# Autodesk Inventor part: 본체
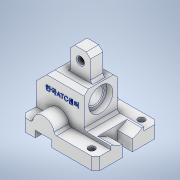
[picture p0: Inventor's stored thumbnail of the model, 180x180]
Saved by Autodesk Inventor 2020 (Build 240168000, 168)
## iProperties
Created: 2022-08
Part Number: 본체
Material: 알루미늄 6061
Document SubType Name: Modeling
Designer: com
Density: 2.7 g/cm^3
Appearance: 알루미늄 - 평지
Mass: 499.243 g
Surface Area: 337.564 cm^2
Volume: 184.905 cm^3
Author: com
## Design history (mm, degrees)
sketch "스케치1"
  geometry: L1 (18, 60)-(58, 60); L2 (58, 60)-(58, 19); L3 (58, 19)-(90, 19); L4 (90, 19)-(90, 0); L5 (90, 0)-(0, 0); L6 (0, 0)-(0, 42); L7 (0, 42)-(18, 60); 1 further point
  constraints: 14 end point, 5 perpendicular, 1 horizontal
  dimensions: "d0" = 45 deg angle of L1 L7; "d1" = 90 distance between parallel lines of L4 L6; "d2" = 0 distance from line of point (0, 0) L6; "d3" = 18 distance from line of L1 L6.end; "d4" = 60 distance between parallel lines of L1 L5; "d5" = 0 distance from line of point (0, 0) L5; "d6" = 32 distance between parallel lines of L4 L2; "d7" = 19 distance between parallel lines of L5 L3
extrude "돌출1" new body sketch "스케치1" stored distance "d8" = 40; taper "d9" = 0 deg
sketch "스케치3"
  geometry: L1 (0, 42)-(0, 0) reference; L2 (90, 19)-(90, 0) reference; L3 (0, 0)-(90, 0); L4 (90, 0)-(90, 15); L5 (0, 15)-(0, 0); L6 (90, 15)-(40, 15); L7 (14, 15)-(0, 15); A1 r 13 centre (27, 15) between (40, 15) and (14, 15); 2 further points
  constraints: 10 end point, 3 parallel, 2 point on circle, 2 point on line, 1 centre point, 1 horizontal, 1 perpendicular
  dimensions: "d11" = 26 diameter of A1; "d12" = 27 distance from line of A1.centre L1; "d13" = 15 distance between parallel lines of L3 L7; "d14" = 15 distance between parallel lines of L3 L6
extrude "돌출2" join sketch "스케치3" stored distance "d15" = 76; taper "d16" = 0 deg
sketch "스케치4"
  geometry: L1 (17, 8)-(37, 8); L2 (37, 8)-(37, -5.385); L3 (37, -5.385)-(17, -5.385); L4 (17, -5.385)-(17, 8); L5 (0, 0)-(0, 15) reference; L6 (90, 0)-(0, 0) reference; 1 further point
  constraints: 8 end point, 2 parallel, 1 horizontal, 1 midpoint, 1 perpendicular
  dimensions: "d17" = 20 distance between parallel lines of L2 L4; "d18" = 27 distance from line of point (27, 8) L5; "d19" = 8 distance between parallel lines of L1 L6
extrude "돌출3" cut sketch "스케치4" extent not by distance; stored distance "d20" = 38; taper "d21" = 0 deg
sketch "스케치5"
  geometry: L1 (18, 60)-(58, 60) reference; L2 (29, 90)-(53, 90); L3 (53, 90)-(53, 60); L4 (53, 60)-(29, 60); L5 (29, 60)-(29, 90); L6 (58, 19)-(58, 60) reference; L7 (37, 0)-(90, 0) reference; C1 r 4 at (41, 77); 2 further points
  constraints: 8 end point, 2 parallel, 1 centre point, 1 horizontal, 1 perpendicular, 1 point on line
  dimensions: "d22" = 30 distance of L4.end L2.start; "d23" = 24 distance of L2.start L2.end; "d24" = 5 distance between parallel lines of L6 L3; "d25" = 8 diameter of C1; "d26" = 12 distance from line of L5 C1.centre; "d27" = 77 distance from line of L7 C1.centre
extrude "돌출4" join sketch "스케치5" stored distance "d28" = 15; taper "d29" = 0 deg
chamfer "모따기1" distance "d30" = 5; stored, may be unused: second distance "d31" = 2, angle "d32" = 45 deg
fillet "모깎기1" dims "d33" = 3
fillet "모깎기2" dims "d34" = 3
chamfer "모따기2" distance "d35" = 5; stored, may be unused: second distance "d36" = 2, angle "d37" = 45 deg
sketch "스케치6"
  geometry: L1 (47.284, 53)-(47.284, -13) reference; 3 further points
  dimensions: "d38" = 30 vertical distance of point (34.284, 50) point (-42.716, 20); "d39" = 60 distance of point (34.284, -10) point (34.284, 50); "d40" = 13 distance from line of L1 point (34.284, 50); "d41" = 13 distance from line of L1 point (34.284, -10)
hole "구멍1" sketch "스케치6" at (34.284, -10), (34.284, 50) diameter "d42" = 4.5; stored, may be unused: countersink angle "d46" = 90 deg, drill point angle "d48" = 118 deg; dims "d43" = 6, "d44" = 8, "d45" = 4.4, "d47" = 8
chamfer "모따기3" distance "d49" = 5; stored, may be unused: second distance "d50" = 2, angle "d51" = 45 deg
sketch "스케치8"
  geometry: L1 (60.58, 42)-(-5.69, 42); L2 (60.58, 42)-(67.958, 42); L3 (37, 0)-(85, 0) reference; L4 (60.58, 42)-(60.58, 56.5); L5 (60.58, 56.5)-(51, 56.5); L6 (51, 56.5)-(51, 52); L7 (51, 52)-(-5.69, 52); L8 (-5.69, 52)-(-5.69, 42); L9 (58, 19)-(58, 55) reference; 1 further point
  constraints: 14 end point, 4 perpendicular, 2 horizontal, 1 vertical
  dimensions: "d53" = 42 distance between parallel lines of L2 L3; "d54" = 29 diameter of L5 L2; "d55" = 20 diameter of L7 L2; "d56" = 7 distance between parallel lines of L6 L9
revolve "회전1" sketch "스케치8" stored, may be unused: angle "d57" = 90 deg
chamfer "모따기4" distance "d58" = 1; stored, may be unused: second distance "d59" = 2, angle "d60" = 45 deg
sketch "스케치9"
  geometry: L1 (14, -5.373)-(14, -22.836); L2 (26, -5.373)-(26, -22.836); L3 (14, -22.836)-(26, -22.836); C1 r 10 at (20, 23) reference; A1 r 29 centre (20, 23) between (14, -5.373) and (26, -5.373); 1 further point
  constraints: 6 end point, 2 point on circle, 2 vertical, 1 centre point, 1 coincident, 1 horizontal
  dimensions: "d61" = 58 diameter of A1; "d62" = 6 distance from line of point (20, -19) L1; "d63" = 12 distance between parallel lines of L2 L1
extrude "돌출5" cut sketch "스케치9" distance "d64" = 18; taper "d65" = 0 deg
chamfer "모따기5" distance "d66" = 1; stored, may be unused: second distance "d67" = 2, angle "d68" = 45 deg
fillet "모깎기3" dims "d69" = 3
sketch "스케치10"
  geometry: L1 (58, 22)-(58, 55) reference; L2 (58, 60)-(18, 60) reference; 2 further points
  constraints: 1 other
  dimensions: "d70" = 26 distance from line of L1 point (32, 42); "d71" = 18 distance from line of L2 point (32, 42)
feature "엠보싱1" sketch "스케치10" dims "d72" = 0.5, "d73" = 0
node "솔리드1"
feature "A9D066F2-1C7D-4E18-AEED-F7BC21143FA4" dims "d42" = 4.5, "d43" = 6, "d44" = 8, "d45" = 4.4, "d46" = 90 deg, "d47" = 8, "d48" = 118 deg
other parameters: "d10" = 15
